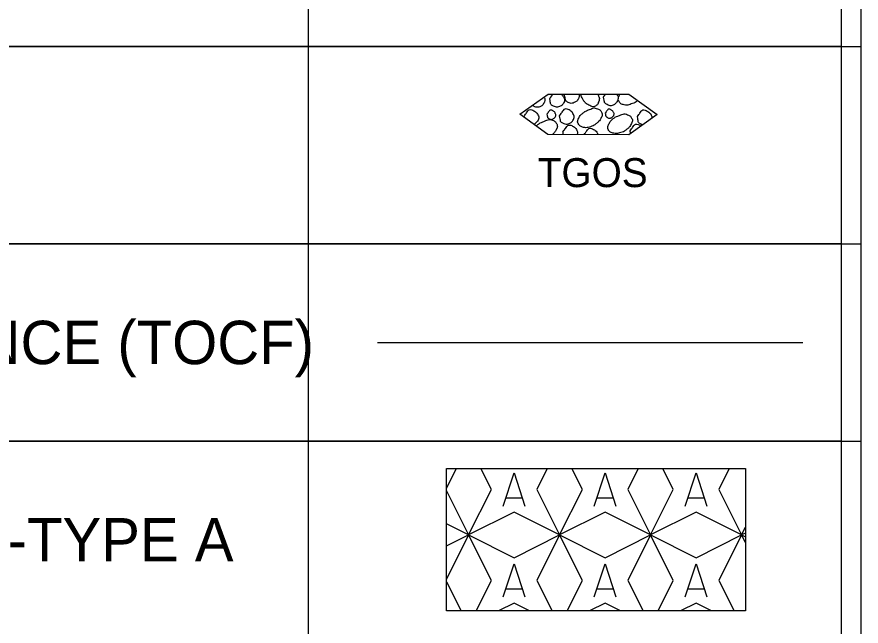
# Model space of a CAD drawing. Extents: x 1.3 to 34, y 0 to 22.5.
# Drawn here: x 16.062 to 18.2, y 12.856 to 14.4 of the extents above; entities that cross this region are included whole.
import ezdxf

# ---------------------------------------------------------------- set-up
doc = ezdxf.new("R2010")
doc.units = 0
for name, color, linetype in [('ANNO-SYMB', 7, 'Continuous'), ('ANNO-TABL', 7, 'Continuous'), ('USER-LINE', 7, 'Continuous')]:
    doc.layers.add(name, color=color, linetype=linetype)

msp = doc.modelspace()

# ---------------------------------------------------------------- linework, layer by layer
at = {"layer": 'ANNO-SYMB'}
for p, q in [((16.975, 13.575), (18.052, 13.575)), ((17.1747, 13.2553), (17.15, 13.2058)), ((17.2635, 13.2024), (17.237, 13.2553)), ((17.4051, 13.2553), (17.3787, 13.2024)), ((17.4939, 13.2024), (17.4674, 13.2553)), ((17.6355, 13.2553), (17.6091, 13.2024)), ((17.7243, 13.2024), (17.6978, 13.2553)), ((17.8659, 13.2553), (17.8395, 13.2024)), ((17.15, 13.1989), (17.2059, 13.0872)), ((17.2059, 13.0872), (17.2635, 13.2024)), ((17.3787, 13.2024), (17.4363, 13.0872)), ((17.4363, 13.0872), (17.4939, 13.2024)), ((17.6091, 13.2024), (17.6667, 13.0872)), ((17.6667, 13.0872), (17.7243, 13.2024)), ((17.8395, 13.2024), (17.8971, 13.0872)), ((17.3419, 13.1802), (17.3002, 13.1802)), ((17.5723, 13.1802), (17.5306, 13.1802)), ((17.8027, 13.1802), (17.761, 13.1802)), ((17.3211, 13.1448), (17.2059, 13.0872)), ((17.4363, 13.0872), (17.3211, 13.1448)), ((17.5515, 13.1448), (17.4363, 13.0872)), ((17.6667, 13.0872), (17.5515, 13.1448)), ((17.7819, 13.1448), (17.6667, 13.0872)), ((17.8971, 13.0872), (17.7819, 13.1448)), ((17.2059, 13.0872), (17.15, 13.1151)), ((17.15, 13.0592), (17.2059, 13.0872)), ((17.2059, 13.0872), (17.15, 12.9754)), ((17.2059, 13.0872), (17.3211, 13.0296)), ((17.2635, 12.972), (17.2059, 13.0872)), ((17.3211, 13.0296), (17.4363, 13.0872)), ((17.4363, 13.0872), (17.3787, 12.972)), ((17.4363, 13.0872), (17.5515, 13.0296)), ((17.4939, 12.972), (17.4363, 13.0872)), ((17.5515, 13.0296), (17.6667, 13.0872)), ((17.6667, 13.0872), (17.6091, 12.972)), ((17.6667, 13.0872), (17.7819, 13.0296)), ((17.7243, 12.972), (17.6667, 13.0872)), ((17.7819, 13.0296), (17.8971, 13.0872)), ((17.8971, 13.0872), (17.8395, 12.972)), ((17.8971, 13.0872), (17.9068, 13.1066)), ((17.9068, 13.092), (17.8971, 13.0872)), ((17.8971, 13.0872), (17.9068, 13.0823)), ((17.9068, 13.0678), (17.8971, 13.0872)), ((17.15, 12.9685), (17.1869, 12.8947)), ((17.2249, 12.8947), (17.2635, 12.972)), ((17.3787, 12.972), (17.4173, 12.8947)), ((17.4553, 12.8947), (17.4939, 12.972)), ((17.6091, 12.972), (17.6477, 12.8947)), ((17.6857, 12.8947), (17.7243, 12.972)), ((17.8395, 12.972), (17.8781, 12.8947)), ((17.3419, 12.9498), (17.3002, 12.9498)), ((17.5723, 12.9498), (17.5306, 12.9498)), ((17.8027, 12.9498), (17.761, 12.9498)), ((17.3211, 12.9144), (17.2818, 12.8947)), ((17.3603, 12.8947), (17.3211, 12.9144)), ((17.5515, 12.9144), (17.5122, 12.8947)), ((17.5907, 12.8947), (17.5515, 12.9144)), ((17.7819, 12.9144), (17.7426, 12.8947)), ((17.8211, 12.8947), (17.7819, 12.9144))]:
    msp.add_line(p, q, dxfattribs=at)
for points in [[(17.4072, 14.2046), (17.612, 14.204), (17.6833, 14.1526), (17.6117, 14.1016), (17.4069, 14.1021), (17.3357, 14.1536)], [(17.15, 13.2553), (17.9068, 13.2553), (17.9068, 12.8947), (17.15, 12.8947)]]:
    msp.add_lwpolyline(points, close=True, dxfattribs=at)
for points in [[(17.2936, 13.1604), (17.3214, 13.2444), (17.3485, 13.1604)], [(17.524, 13.1604), (17.5518, 13.2444), (17.5789, 13.1604)], [(17.7544, 13.1604), (17.7822, 13.2444), (17.8093, 13.1604)], [(17.2936, 12.93), (17.3214, 13.014), (17.3485, 12.93)], [(17.524, 12.93), (17.5518, 13.014), (17.5789, 12.93)], [(17.7544, 12.93), (17.7822, 13.014), (17.8093, 12.93)]]:
    msp.add_lwpolyline(points, dxfattribs=at)
for points, degree in [([(17.4402, 14.2045), (17.443, 14.2021), (17.4451, 14.199), (17.4469, 14.196), (17.4494, 14.1916), (17.4488, 14.1852), (17.4457, 14.1805), (17.4432, 14.1768), (17.44, 14.1743), (17.4361, 14.1728), (17.4313, 14.1709), (17.4254, 14.1714), (17.4207, 14.174), (17.4177, 14.1756), (17.4142, 14.1774), (17.4135, 14.1806), (17.4128, 14.1846), (17.412, 14.1885), (17.4112, 14.1925)], 3), ([(17.4112, 14.1925), (17.414, 14.1965), (17.4168, 14.2005), (17.4196, 14.2045)], 2), ([(17.4851, 14.2044), (17.4866, 14.2), (17.4854, 14.195), (17.4826, 14.1905), (17.4801, 14.1866), (17.4768, 14.1844), (17.473, 14.1828), (17.4684, 14.1808), (17.4627, 14.1809), (17.4582, 14.1834), (17.4551, 14.1852), (17.4517, 14.1873), (17.451, 14.1906), (17.4503, 14.1946), (17.4495, 14.1985), (17.4487, 14.2025)], 3), ([(17.5334, 14.2042), (17.5341, 14.2024), (17.5348, 14.2005), (17.5355, 14.1987), (17.5375, 14.1937), (17.5364, 14.1879), (17.5343, 14.1826), (17.5329, 14.1791), (17.5305, 14.1762), (17.5271, 14.1743), (17.523, 14.172), (17.5175, 14.1729), (17.5135, 14.175), (17.5076, 14.178), (17.5019, 14.1812), (17.498, 14.1869), (17.4942, 14.1925), (17.4914, 14.1982), (17.4895, 14.2044)], 3), ([(17.5474, 14.1969), (17.5491, 14.1993), (17.5508, 14.2018), (17.5525, 14.2042)], 2), ([(17.5808, 14.2041), (17.5817, 14.2029), (17.5825, 14.2016), (17.5831, 14.2004), (17.5855, 14.1959), (17.5843, 14.1898), (17.5813, 14.1849), (17.5789, 14.181), (17.5757, 14.1783), (17.5718, 14.1766), (17.5672, 14.1746), (17.5614, 14.1751), (17.5569, 14.1778), (17.5539, 14.1796), (17.5504, 14.1817), (17.5498, 14.185), (17.549, 14.1889), (17.5482, 14.1929), (17.5474, 14.1969)], 3), ([(17.6342, 14.188), (17.6338, 14.1877), (17.6334, 14.1874), (17.6331, 14.1871), (17.6277, 14.1829), (17.621, 14.1806), (17.6146, 14.1783), (17.6092, 14.1763), (17.603, 14.1762), (17.5973, 14.1777), (17.5933, 14.1788), (17.5897, 14.181), (17.5873, 14.1849), (17.5845, 14.1892), (17.5849, 14.1944), (17.5867, 14.1986), (17.5875, 14.2004), (17.5883, 14.2023), (17.5892, 14.2041)], 3), ([(17.3967, 14.1971), (17.397, 14.1966), (17.3973, 14.196), (17.3975, 14.1955), (17.3998, 14.1909), (17.3988, 14.1849), (17.3957, 14.18), (17.3933, 14.1762), (17.3901, 14.1736), (17.3862, 14.1723), (17.3814, 14.1708), (17.3757, 14.1712), (17.3713, 14.1736), (17.3699, 14.1743), (17.3685, 14.1751), (17.3672, 14.176)], 3), ([(17.3462, 14.148), (17.3494, 14.1526), (17.3526, 14.1571), (17.3558, 14.1617), (17.3586, 14.1658), (17.3662, 14.1648), (17.3707, 14.1623), (17.3752, 14.1597), (17.379, 14.1561), (17.3813, 14.1515), (17.3838, 14.1468), (17.3834, 14.1403), (17.3801, 14.1361), (17.3776, 14.1327), (17.3748, 14.1298), (17.3711, 14.128)], 3), ([(17.404, 14.1532), (17.4059, 14.156), (17.4079, 14.1588), (17.4099, 14.1616), (17.4118, 14.1641), (17.4166, 14.1638), (17.4194, 14.1621), (17.422, 14.1605), (17.4241, 14.1583), (17.4254, 14.1556), (17.4268, 14.1527), (17.4267, 14.1489), (17.4248, 14.1461), (17.4232, 14.1438), (17.4212, 14.1422), (17.4188, 14.1413), (17.416, 14.1402), (17.4126, 14.1403), (17.4099, 14.1419), (17.4081, 14.143), (17.4062, 14.1442), (17.4057, 14.1461), (17.4051, 14.1485), (17.4045, 14.1509), (17.404, 14.1532)], 3), ([(17.4355, 14.1496), (17.4389, 14.1541), (17.4422, 14.1587), (17.4456, 14.1632), (17.4486, 14.1672), (17.4561, 14.1669), (17.4605, 14.1644), (17.4651, 14.1618), (17.4688, 14.1578), (17.4712, 14.1531), (17.4735, 14.1483), (17.4732, 14.1422), (17.4699, 14.1376), (17.4674, 14.134), (17.4642, 14.1314), (17.4604, 14.1299), (17.4556, 14.128), (17.4497, 14.1286), (17.4449, 14.1311), (17.442, 14.1327), (17.4384, 14.1345), (17.4378, 14.1377), (17.437, 14.1417), (17.4363, 14.1456), (17.4355, 14.1496)], 3), ([(17.5003, 14.1607), (17.5063, 14.1631), (17.5122, 14.1655), (17.5182, 14.1678), (17.5234, 14.1699), (17.5294, 14.1685), (17.5349, 14.166), (17.5383, 14.1644), (17.5408, 14.162), (17.5426, 14.1588), (17.5448, 14.1547), (17.5441, 14.1492), (17.5419, 14.1451), (17.5389, 14.1395), (17.5354, 14.1346), (17.53, 14.1303), (17.5241, 14.1256), (17.5182, 14.1228), (17.5115, 14.1208), (17.506, 14.1192), (17.4999, 14.1192), (17.4943, 14.1209), (17.4905, 14.122), (17.4873, 14.124), (17.4848, 14.1275), (17.4818, 14.1316), (17.4818, 14.1371), (17.4836, 14.1411), (17.4857, 14.1456), (17.4881, 14.1505), (17.492, 14.1536), (17.495, 14.156), (17.498, 14.1584), (17.5009, 14.1607)], 3), ([(17.5515, 14.1558), (17.5535, 14.1586), (17.5555, 14.1614), (17.5575, 14.1641), (17.5592, 14.1666), (17.5637, 14.1662), (17.5664, 14.1647), (17.5691, 14.1632), (17.5714, 14.1609), (17.5729, 14.1582), (17.5744, 14.1553), (17.5743, 14.1515), (17.5723, 14.1486), (17.5707, 14.1464), (17.5687, 14.1447), (17.5663, 14.1439), (17.5635, 14.1429), (17.5601, 14.1434), (17.5574, 14.1451), (17.5556, 14.1462), (17.5538, 14.1474), (17.5533, 14.1493), (17.5527, 14.1515), (17.5521, 14.1536), (17.5515, 14.1558)], 3), ([(17.6336, 14.1473), (17.6367, 14.1518), (17.6399, 14.1564), (17.6431, 14.1609), (17.646, 14.165), (17.6537, 14.1641), (17.658, 14.1615), (17.6623, 14.1589), (17.6665, 14.1557), (17.6687, 14.1508), (17.6698, 14.1483), (17.6703, 14.1458), (17.6701, 14.1433)], 3), ([(17.3866, 14.1313), (17.3926, 14.1336), (17.3986, 14.136), (17.4045, 14.1384), (17.4097, 14.1404), (17.4158, 14.1397), (17.4212, 14.1371), (17.4247, 14.1355), (17.4272, 14.1328), (17.4289, 14.1294), (17.4309, 14.1253), (17.4309, 14.1201), (17.4288, 14.1163), (17.426, 14.1112), (17.4229, 14.106), (17.4184, 14.1021)], 3), ([(17.5764, 14.1457), (17.5824, 14.148), (17.5884, 14.1504), (17.5943, 14.1527), (17.5995, 14.1548), (17.6055, 14.1534), (17.611, 14.1509), (17.6144, 14.1493), (17.6169, 14.147), (17.6187, 14.1438), (17.621, 14.1396), (17.6207, 14.1341), (17.6186, 14.1301), (17.6157, 14.1244), (17.6121, 14.1195), (17.6067, 14.1152), (17.6008, 14.1106), (17.5949, 14.1077), (17.5882, 14.1058), (17.5827, 14.1041), (17.5766, 14.1042), (17.571, 14.1058), (17.5671, 14.1069), (17.5636, 14.1088), (17.5609, 14.1124), (17.5577, 14.1167), (17.5583, 14.1224), (17.5603, 14.1267), (17.5623, 14.1308), (17.5645, 14.1354), (17.5681, 14.1385), (17.5711, 14.1411), (17.5741, 14.1437), (17.577, 14.1462)], 3), ([(17.6466, 14.1264), (17.6451, 14.1269), (17.6438, 14.1275), (17.6424, 14.1282), (17.6394, 14.1299), (17.6358, 14.1321), (17.6353, 14.1354), (17.6347, 14.1393), (17.6341, 14.1433), (17.6336, 14.1473)], 3), ([(17.3771, 14.1237), (17.3775, 14.1241), (17.3779, 14.1244), (17.3783, 14.1248), (17.3813, 14.1271), (17.3843, 14.1295), (17.3872, 14.1319)], 3), ([(17.4449, 14.1091), (17.4481, 14.1135), (17.4512, 14.1178), (17.4544, 14.1222), (17.4574, 14.1262), (17.465, 14.1259), (17.4693, 14.1233), (17.4738, 14.1207), (17.4778, 14.1171), (17.48, 14.112), (17.4814, 14.1087), (17.4818, 14.1052), (17.4811, 14.1019)], 3), ([(17.4985, 14.1019), (17.5013, 14.1058), (17.504, 14.1098), (17.5068, 14.1137), (17.5097, 14.1179), (17.518, 14.1177), (17.5222, 14.1149), (17.5265, 14.112), (17.5307, 14.1083), (17.5329, 14.1035), (17.5332, 14.103), (17.5334, 14.1024), (17.5336, 14.1018)], 3), ([(17.615, 14.111), (17.6182, 14.1156), (17.6214, 14.1202), (17.6246, 14.1247), (17.6275, 14.1289), (17.6356, 14.1279), (17.64, 14.1253), (17.6409, 14.1247), (17.6418, 14.1242), (17.6426, 14.1236)], 3), ([(17.4459, 14.102), (17.4456, 14.1044), (17.4452, 14.1068), (17.4449, 14.1091)], 2), ([(17.6162, 14.1048), (17.6158, 14.1069), (17.6154, 14.109), (17.615, 14.111)], 2)]:
    msp.add_open_spline(points, degree=degree, dxfattribs=at)
at = {"layer": 'ANNO-TABL'}
for p, q in [((2, 14.325), (18.2, 14.325)), ((2, 13.825), (18.2, 13.825)), ((2, 13.325), (18.2, 13.325))]:
    msp.add_line(p, q, dxfattribs=at)
msp.add_lwpolyline([(12.8, 7.825), (18.2, 7.825), (18.2, 19.825), (12.8, 19.825)], close=True, dxfattribs=at)
at = {"layer": 'USER-LINE'}
for p, q in [((16.8, 14.325), (16.8, 14.825)), ((18.15, 14.325), (18.15, 14.825)), ((16.8, 14.325), (12.85, 14.325)), ((16.8, 13.825), (16.8, 14.325)), ((18.15, 14.325), (16.8, 14.325)), ((18.15, 13.825), (18.15, 14.325)), ((16.8, 13.825), (12.85, 13.825)), ((18.15, 13.825), (16.8, 13.825)), ((16.8, 13.325), (16.8, 13.825)), ((18.15, 13.325), (18.15, 13.825)), ((16.8, 13.325), (12.85, 13.325)), ((18.15, 13.325), (16.8, 13.325)), ((16.8, 12.825), (16.8, 13.325)), ((18.15, 12.825), (18.15, 13.325))]:
    msp.add_line(p, q, dxfattribs=at)

# ---------------------------------------------------------------- texts
at = {"layer": 'ANNO-SYMB'}
msp.add_text('TGOS', height=0.07344, dxfattribs=at).set_placement((17.381, 13.9687))
at = {"layer": 'ANNO-TABL'}
for s, p in [('TEMPORARY ORANGE CONSTRUCTION FENCE (TOCF)', (12.9, 13.52)), ('TEMPORARY SOIL STABILIZATION MATTING-TYPE A', (12.9, 13.02))]:
    msp.add_text(s, height=0.11, dxfattribs=at).set_placement(p)

doc.saveas('drawing.dxf')
